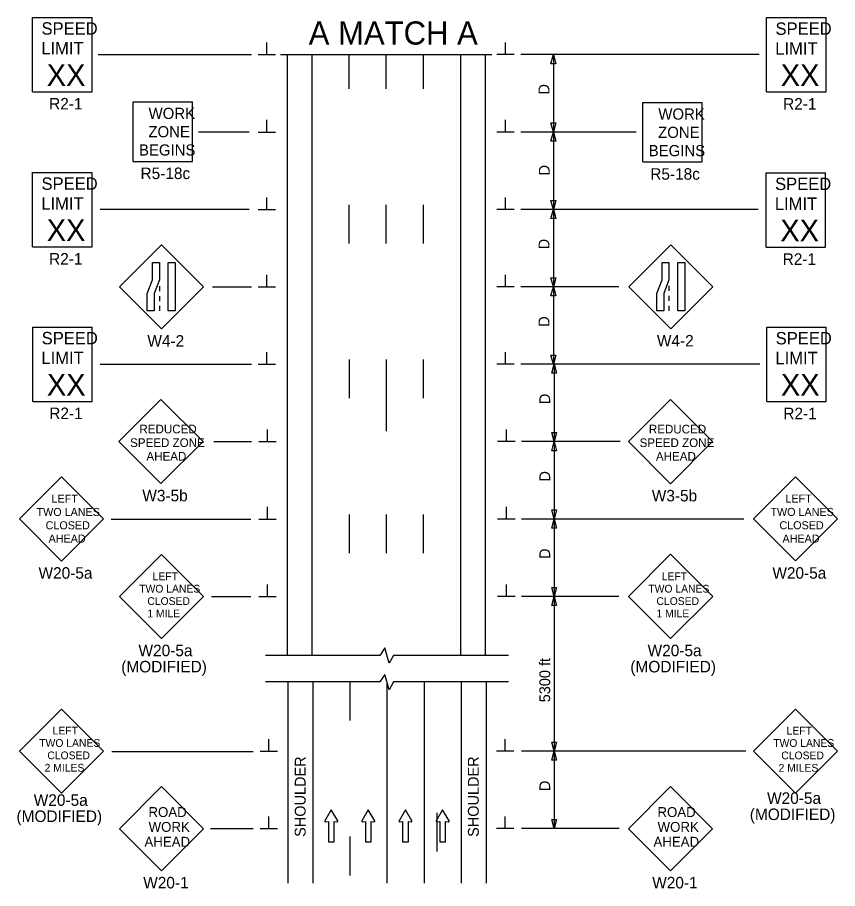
# Model space of a CAD drawing. Extents: x 16630 to 19509, y 5576 to 6998.
# Drawn here: x 17841 to 18371, y 6359 to 6921 of the extents above; entities that cross this region are included whole.
import ezdxf

# ---------------------------------------------------------------- set-up
doc = ezdxf.new("R2010")
doc.units = 0
for name, color, linetype in [('ALI_LEGAL_EX', 7, 'Continuous'), ('MT_SCRATCH_LEVEL_E', 7, 'Continuous'), ('PAVT_EDGE_EX', 7, 'Continuous'), ('TRAFFIC_SIGNS_PR', 7, 'Continuous'), ('TYPICAL_TEXT_DIMEN_PR', 7, 'Continuous')]:
    doc.layers.add(name, color=color, linetype=linetype)

msp = doc.modelspace()

# ---------------------------------------------------------------- linework, layer by layer
at = {"layer": 'ALI_LEGAL_EX'}
for p, q in [((18080.13, 6492.04), (18080.13, 6361.96)), ((18104.13, 6492.04), (18104.13, 6361.96))]:
    msp.add_line(p, q, dxfattribs=at)
for points in [[(18055.61, 6875.22), (18055.61, 6897.24)], [(18079.61, 6875.22), (18079.61, 6897.24)], [(18103.61, 6875.22), (18103.61, 6897.24)], [(18055.61, 6775.22), (18055.61, 6800.22)], [(18079.61, 6775.22), (18079.61, 6800.22)], [(18103.61, 6775.22), (18103.61, 6800.22)], [(18055.61, 6700.22), (18055.61, 6675.22)], [(18079.61, 6700.22), (18079.61, 6675.22)], [(18103.61, 6675.22), (18103.61, 6700.22)], [(18079.61, 6679.08), (18079.61, 6654.08)], [(18055.61, 6600.22), (18055.61, 6575.22)], [(18079.61, 6600.22), (18079.61, 6575.22)], [(18103.61, 6575.22), (18103.61, 6600.22)], [(18056.13, 6492.04), (18056.13, 6467.04)], [(18080.13, 6492.04), (18080.13, 6467.04)], [(18104.13, 6492.04), (18104.13, 6467.04)], [(18112.27, 6407.39), (18112.27, 6382.39)], [(18056.13, 6392.04), (18056.13, 6367.04)], [(18080.13, 6392.04), (18080.13, 6367.04)], [(18104.13, 6392.04), (18104.13, 6367.04)]]:
    msp.add_lwpolyline(points, dxfattribs=at)
at = {"layer": 'MT_SCRATCH_LEVEL_E'}
for p, q in [((18044.13, 6409.47), (18040.02, 6402.23)), ((18048.27, 6402.23), (18044.13, 6409.47)), ((18068.03, 6409.47), (18063.92, 6402.23)), ((18072.18, 6402.23), (18068.03, 6409.47)), ((18092.03, 6409.47), (18087.92, 6402.23)), ((18096.18, 6402.23), (18092.03, 6409.47)), ((18116.08, 6409.47), (18111.97, 6402.23)), ((18120.23, 6402.23), (18116.08, 6409.47)), ((18040.5, 6401.54), (18042.28, 6401.86)), ((18042.28, 6401.86), (18042.28, 6388.6)), ((18046.02, 6388.6), (18046.02, 6401.86)), ((18046.02, 6401.86), (18047.79, 6401.54)), ((18064.4, 6401.54), (18066.18, 6401.86)), ((18066.18, 6401.86), (18066.18, 6388.6)), ((18069.92, 6388.6), (18069.92, 6401.86)), ((18069.92, 6401.86), (18071.7, 6401.54)), ((18088.4, 6401.54), (18090.18, 6401.86)), ((18090.18, 6401.86), (18090.18, 6388.6)), ((18093.92, 6388.6), (18093.92, 6401.86)), ((18093.92, 6401.86), (18095.7, 6401.54)), ((18112.46, 6401.54), (18114.23, 6401.86)), ((18114.23, 6401.86), (18114.23, 6388.6)), ((18117.97, 6388.6), (18117.97, 6401.86)), ((18117.97, 6401.86), (18119.75, 6401.54)), ((18042.28, 6388.6), (18046.02, 6388.6)), ((18066.18, 6388.6), (18069.92, 6388.6)), ((18090.18, 6388.6), (18093.92, 6388.6)), ((18114.23, 6388.6), (18117.97, 6388.6))]:
    msp.add_line(p, q, dxfattribs=at)
for centre, start, end in [((18040.42, 6402), 150.4248, 279.9638), ((18047.86, 6402), 260.0362, 29.7731), ((18064.33, 6402), 150.4248, 279.9638), ((18071.77, 6402), 260.0362, 29.7731), ((18088.33, 6402), 150.4248, 279.9638), ((18095.77, 6402), 260.0362, 29.7731), ((18112.38, 6402), 150.4248, 279.9638), ((18119.82, 6402), 260.0362, 29.7731)]:
    msp.add_arc(centre, 0.463, start, end, dxfattribs=at)
at = {"layer": 'PAVT_EDGE_EX'}
for p, q in [((18015.61, 6897.24), (18015.61, 6509.16)), ((18031.61, 6897.24), (18031.61, 6509.16)), ((18127.61, 6897.24), (18127.61, 6509.16)), ((18143.61, 6897.24), (18143.61, 6509.16)), ((18016.13, 6492.02), (18016.13, 6361.96)), ((18032.13, 6492.02), (18032.13, 6361.96)), ((18128.13, 6492.02), (18128.13, 6361.96)), ((18144.13, 6492.02), (18144.13, 6361.96))]:
    msp.add_line(p, q, dxfattribs=at)
at = {"layer": 'TRAFFIC_SIGNS_PR'}
for p, q in [((17851.16, 6921.26), (17889.56, 6921.26)), ((17851.16, 6873.26), (17851.16, 6921.26)), ((17889.56, 6873.26), (17889.56, 6921.26)), ((18325.38, 6921.16), (18363.78, 6921.16)), ((18325.38, 6873.16), (18325.38, 6921.16)), ((18363.78, 6873.16), (18363.78, 6921.16)), ((17851.16, 6873.26), (17889.56, 6873.26)), ((18325.38, 6873.16), (18363.78, 6873.16)), ((17916.1, 6828.28), (17916.1, 6866.68)), ((17916.1, 6866.68), (17954.5, 6866.68)), ((17954.5, 6828.28), (17954.5, 6866.68)), ((18245.42, 6827.87), (18245.42, 6866.27)), ((18245.42, 6866.27), (18283.82, 6866.27)), ((18283.82, 6827.87), (18283.82, 6866.27)), ((17916.1, 6828.28), (17954.5, 6828.28)), ((18245.42, 6827.87), (18283.82, 6827.87)), ((17851.16, 6821.05), (17889.56, 6821.05)), ((17851.16, 6773.05), (17851.16, 6821.05)), ((17889.56, 6773.05), (17889.56, 6821.05)), ((18325.1, 6820.87), (18363.5, 6820.87)), ((18325.1, 6772.87), (18325.1, 6820.87)), ((18363.5, 6772.87), (18363.5, 6820.87)), ((17851.16, 6773.05), (17889.56, 6773.05)), ((17934.36, 6774.31), (17907.21, 6747.16)), ((17961.52, 6747.16), (17934.36, 6774.31)), ((18263.56, 6774.43), (18236.41, 6747.28)), ((18290.71, 6747.28), (18263.56, 6774.43)), ((18325.1, 6772.87), (18363.5, 6772.87)), ((17933.12, 6747.65), (17933.12, 6744.45)), ((18262.31, 6747.77), (18262.31, 6744.57)), ((17907.21, 6747.16), (17934.36, 6720.01)), ((17934.36, 6720.01), (17961.52, 6747.16)), ((18236.41, 6747.28), (18263.56, 6720.13)), ((18263.56, 6720.13), (18290.71, 6747.28)), ((17933.12, 6741.25), (17933.12, 6738.05)), ((18262.31, 6741.37), (18262.31, 6738.17)), ((17933.12, 6734.85), (17933.12, 6731.65)), ((18262.31, 6734.97), (18262.31, 6731.77)), ((17851.27, 6721.23), (17889.67, 6721.23)), ((17851.27, 6673.23), (17851.27, 6721.23)), ((17889.67, 6673.23), (17889.67, 6721.23)), ((18325.5, 6721.17), (18363.9, 6721.17)), ((18325.5, 6673.17), (18325.5, 6721.17)), ((18363.9, 6673.17), (18363.9, 6721.17)), ((17934.1, 6674.41), (17906.95, 6647.26)), ((17961.26, 6647.26), (17934.1, 6674.41)), ((18263.27, 6674.37), (18236.11, 6647.21)), ((18290.42, 6647.21), (18263.27, 6674.37)), ((17851.27, 6673.23), (17889.67, 6673.23)), ((18325.5, 6673.17), (18363.9, 6673.17)), ((17906.95, 6647.26), (17934.1, 6620.1)), ((17934.1, 6620.1), (17961.26, 6647.26)), ((18236.11, 6647.21), (18263.27, 6620.06)), ((18263.27, 6620.06), (18290.42, 6647.21)), ((17869.85, 6624.41), (17842.7, 6597.26)), ((17897.01, 6597.26), (17869.85, 6624.41)), ((18343.98, 6624.43), (18316.82, 6597.28)), ((18371.13, 6597.28), (18343.98, 6624.43)), ((17842.7, 6597.26), (17869.85, 6570.11)), ((17869.85, 6570.11), (17897.01, 6597.26)), ((18316.82, 6597.28), (18343.98, 6570.12)), ((18343.98, 6570.12), (18371.13, 6597.28)), ((17934.46, 6574.42), (17907.27, 6547.24)), ((17961.65, 6547.24), (17934.46, 6574.42)), ((18263.39, 6574.43), (18236.2, 6547.24)), ((18290.58, 6547.24), (18263.39, 6574.43)), ((17907.27, 6547.24), (17934.46, 6520.05)), ((17934.46, 6520.05), (17961.65, 6547.24)), ((18236.2, 6547.24), (18263.39, 6520.05)), ((18263.39, 6520.05), (18290.58, 6547.24)), ((17869.86, 6474.47), (17842.68, 6447.28)), ((17897.05, 6447.28), (17869.86, 6474.47)), ((18344.06, 6474.42), (18316.87, 6447.24)), ((18371.24, 6447.24), (18344.06, 6474.42)), ((17842.68, 6447.28), (17869.86, 6420.1)), ((17869.86, 6420.1), (17897.05, 6447.28)), ((18316.87, 6447.24), (18344.06, 6420.05)), ((18344.06, 6420.05), (18371.24, 6447.24)), ((17934.47, 6424.35), (17907.32, 6397.2)), ((17961.62, 6397.2), (17934.47, 6424.35)), ((18263.32, 6424.35), (18236.17, 6397.2)), ((18290.47, 6397.2), (18263.32, 6424.35)), ((17907.32, 6397.2), (17934.47, 6370.05)), ((17934.47, 6370.05), (17961.62, 6397.2)), ((18236.17, 6397.2), (18263.32, 6370.05)), ((18263.32, 6370.05), (18290.47, 6397.2))]:
    msp.add_line(p, q, dxfattribs=at)
for points in [[(17933.12, 6762.9), (17933.12, 6751.72), (17929.77, 6742.83), (17929.77, 6731.65), (17925.28, 6731.65), (17925.28, 6742.83), (17928.62, 6751.72), (17928.62, 6762.9)], [(17943.25, 6762.9), (17943.25, 6731.65), (17938.76, 6731.65), (17938.76, 6762.9)], [(18262.31, 6763.02), (18262.31, 6751.84), (18258.97, 6742.95), (18258.97, 6731.77), (18254.47, 6731.77), (18254.47, 6742.95), (18257.82, 6751.84), (18257.82, 6763.02)], [(18272.45, 6763.02), (18272.45, 6731.77), (18267.96, 6731.77), (18267.96, 6763.02)]]:
    msp.add_lwpolyline(points, close=True, dxfattribs=at)
at = {"layer": 'TYPICAL_TEXT_DIMEN_PR'}
for p, q in [((18002.48, 6897.24), (18002.48, 6905.02)), ((18156.73, 6897.24), (18156.73, 6905.02)), ((17893.57, 6897.24), (17992.61, 6897.24)), ((17996.86, 6897.24), (18008.11, 6897.24)), ((18011.28, 6897.24), (18147.93, 6897.24)), ((18162.36, 6897.24), (18151.11, 6897.24)), ((18320.48, 6897.24), (18166.61, 6897.24)), ((18186.04, 6891.37), (18187.61, 6897.24)), ((18187.61, 6897.24), (18187.61, 6847.24)), ((18187.61, 6897.24), (18189.18, 6891.37)), ((18187.61, 6891.37), (18186.04, 6891.37)), ((18189.18, 6891.37), (18187.61, 6891.37)), ((18002.48, 6847.24), (18002.48, 6855.02)), ((18156.73, 6847.24), (18156.73, 6855.02)), ((18187.61, 6847.24), (18186.04, 6853.1)), ((18186.04, 6853.1), (18187.61, 6853.1)), ((18187.61, 6853.1), (18189.18, 6853.1)), ((18189.18, 6853.1), (18187.61, 6847.24)), ((17991.11, 6847.24), (17958.31, 6847.24)), ((17996.86, 6847.24), (18008.11, 6847.24)), ((18162.36, 6847.24), (18151.11, 6847.24)), ((18241.03, 6847.24), (18166.61, 6847.24)), ((18186.04, 6841.37), (18187.61, 6847.24)), ((18187.61, 6847.24), (18189.18, 6841.37)), ((18187.61, 6847.24), (18187.61, 6787.24)), ((18187.61, 6841.37), (18186.04, 6841.37)), ((18189.18, 6841.37), (18187.61, 6841.37)), ((18002.48, 6797.24), (18002.48, 6805.02)), ((18156.73, 6797.24), (18156.73, 6805.02)), ((18187.61, 6797.24), (18186.04, 6803.1)), ((18186.04, 6803.1), (18187.61, 6803.1)), ((18187.61, 6803.1), (18189.18, 6803.1)), ((18189.18, 6803.1), (18187.61, 6797.24)), ((17991.11, 6797.24), (17894.89, 6797.24)), ((17996.86, 6797.24), (18008.11, 6797.24)), ((18162.36, 6797.24), (18151.11, 6797.24)), ((18319.93, 6797.24), (18166.61, 6797.24)), ((18186.04, 6791.37), (18187.61, 6797.24)), ((18187.61, 6797.24), (18187.61, 6747.24)), ((18187.61, 6797.24), (18189.18, 6791.37)), ((18187.61, 6791.37), (18186.04, 6791.37)), ((18189.18, 6791.37), (18187.61, 6791.37)), ((18002.48, 6747.24), (18002.48, 6755.02)), ((18156.73, 6747.24), (18156.73, 6755.02)), ((18187.61, 6747.24), (18186.04, 6753.1)), ((18186.04, 6753.1), (18187.61, 6753.1)), ((18187.61, 6753.1), (18189.18, 6753.1)), ((18189.18, 6753.1), (18187.61, 6747.24)), ((17967.34, 6747.24), (17992.61, 6747.24)), ((17996.86, 6747.24), (18008.11, 6747.24)), ((18162.36, 6747.24), (18151.11, 6747.24)), ((18229.94, 6747.24), (18166.61, 6747.24)), ((18186.04, 6741.37), (18187.61, 6747.24)), ((18187.61, 6747.24), (18187.61, 6697.24)), ((18187.61, 6747.24), (18189.18, 6741.37)), ((18187.61, 6741.37), (18186.04, 6741.37)), ((18189.18, 6741.37), (18187.61, 6741.37)), ((18002.48, 6697.24), (18002.48, 6705.02)), ((18156.73, 6697.24), (18156.73, 6705.02)), ((18187.61, 6697.24), (18186.04, 6703.1)), ((18186.04, 6703.1), (18187.61, 6703.1)), ((18187.61, 6703.1), (18189.18, 6703.1)), ((18189.18, 6703.1), (18187.61, 6697.24)), ((17894.89, 6697.24), (17992.61, 6697.24)), ((17996.86, 6697.24), (18008.11, 6697.24)), ((18162.36, 6697.24), (18151.11, 6697.24)), ((18320.93, 6697.24), (18166.61, 6697.24)), ((18186.56, 6691.37), (18188.13, 6697.24)), ((18188.13, 6697.24), (18188.13, 6647.24)), ((18188.13, 6697.24), (18189.7, 6691.37)), ((18188.13, 6691.37), (18186.56, 6691.37)), ((18189.7, 6691.37), (18188.13, 6691.37)), ((18003, 6647.24), (18003, 6655.02)), ((18157.25, 6647.24), (18157.25, 6655.02)), ((18188.13, 6647.24), (18186.56, 6653.1)), ((18186.56, 6653.1), (18188.13, 6653.1)), ((18188.13, 6653.1), (18189.7, 6653.1)), ((18189.7, 6653.1), (18188.13, 6647.24)), ((17968.25, 6647.24), (17992.61, 6647.24)), ((17997.38, 6647.24), (18008.63, 6647.24)), ((18162.88, 6647.24), (18151.63, 6647.24)), ((18230.83, 6647.24), (18167.13, 6647.24)), ((18186.56, 6641.37), (18188.13, 6647.24)), ((18188.13, 6647.24), (18188.13, 6597.24)), ((18188.13, 6647.24), (18189.7, 6641.37)), ((18188.13, 6641.37), (18186.56, 6641.37)), ((18189.7, 6641.37), (18188.13, 6641.37)), ((18003, 6597.24), (18003, 6605.02)), ((18157.25, 6597.24), (18157.25, 6605.02)), ((18188.13, 6597.24), (18186.56, 6603.1)), ((18186.56, 6603.1), (18188.13, 6603.1)), ((18188.13, 6603.1), (18189.7, 6603.1)), ((18189.7, 6603.1), (18188.13, 6597.24)), ((17901.84, 6597.24), (17992.08, 6597.24)), ((17997.38, 6597.24), (18008.63, 6597.24)), ((18162.88, 6597.24), (18151.63, 6597.24)), ((18310.77, 6597.24), (18167.13, 6597.24)), ((18186.56, 6591.37), (18188.13, 6597.24)), ((18188.13, 6597.24), (18188.13, 6547.24)), ((18188.13, 6597.24), (18189.7, 6591.37)), ((18188.13, 6591.37), (18186.56, 6591.37)), ((18189.7, 6591.37), (18188.13, 6591.37)), ((18003, 6547.24), (18003, 6555.02)), ((18157.25, 6547.24), (18157.25, 6555.02)), ((18188.13, 6547.24), (18186.56, 6553.1)), ((18186.56, 6553.1), (18188.13, 6553.1)), ((18188.13, 6553.1), (18189.7, 6553.1)), ((18189.7, 6553.1), (18188.13, 6547.24)), ((17966.8, 6547.24), (17992.08, 6547.24)), ((17997.38, 6547.24), (18008.63, 6547.24)), ((18162.88, 6547.24), (18151.63, 6547.24)), ((18229.89, 6547.24), (18167.13, 6547.24)), ((18186.56, 6541.37), (18188.13, 6547.24)), ((18188.13, 6547.24), (18188.13, 6447.24)), ((18188.13, 6547.24), (18189.7, 6541.37)), ((18188.13, 6541.37), (18186.56, 6541.37)), ((18189.7, 6541.37), (18188.13, 6541.37)), ((18078.8, 6513.96), (18075.54, 6509.16)), ((18081.54, 6504.02), (18078.8, 6513.96)), ((18075.54, 6509.16), (18001.63, 6509.16)), ((18084.28, 6509.16), (18081.54, 6504.02)), ((18158.63, 6509.16), (18084.28, 6509.16)), ((18078.8, 6496.82), (18075.54, 6492.02)), ((18081.54, 6486.88), (18078.8, 6496.82)), ((18075.54, 6492.02), (18001.63, 6492.02)), ((18084.28, 6492.02), (18081.54, 6486.88)), ((18158.63, 6492.02), (18084.28, 6492.02)), ((18003.75, 6447.24), (18003.75, 6455.02)), ((18156.5, 6447.24), (18156.5, 6455.02)), ((18188.13, 6447.24), (18186.56, 6453.1)), ((18186.56, 6453.1), (18188.13, 6453.1)), ((18188.13, 6453.1), (18189.7, 6453.1)), ((18189.7, 6453.1), (18188.13, 6447.24)), ((17902.39, 6447.08), (17993.62, 6447.08)), ((17998.13, 6447.24), (18009.38, 6447.24)), ((18162.13, 6447.24), (18150.88, 6447.24)), ((18312.04, 6447.24), (18167.13, 6447.24)), ((18186.56, 6441.37), (18188.13, 6447.24)), ((18188.13, 6447.24), (18188.13, 6397.24)), ((18188.13, 6447.24), (18189.7, 6441.37)), ((18188.13, 6441.37), (18186.56, 6441.37)), ((18189.7, 6441.37), (18188.13, 6441.37)), ((18003.75, 6397.24), (18003.75, 6405.02)), ((18156.5, 6397.24), (18156.5, 6405.02)), ((18188.13, 6397.24), (18186.56, 6403.1)), ((18186.56, 6403.1), (18188.13, 6403.1)), ((18188.13, 6403.1), (18189.7, 6403.1)), ((18189.7, 6403.1), (18188.13, 6397.24)), ((17966.08, 6397.24), (17993.62, 6397.24)), ((17998.13, 6397.24), (18009.38, 6397.24)), ((18162.13, 6397.24), (18150.88, 6397.24)), ((18230.07, 6397.24), (18167.13, 6397.24))]:
    msp.add_line(p, q, dxfattribs=at)

# ---------------------------------------------------------------- texts
at = {"layer": 'TRAFFIC_SIGNS_PR'}
for s, height, p in [('SPEED', 8, (17856.93, 6910.13)), ('SPEED', 8, (18331.15, 6910.02)), ('LIMIT', 8, (17856.77, 6897.33)), ('LIMIT', 8, (18330.98, 6897.22)), ('XX', 14.031, (17860.28, 6877.02)), ('XX', 14.031, (18334.49, 6876.91)), ('R2-1', 7.44, (17861.84, 6861.82)), ('R2-1', 7.44, (18336.06, 6861.72)), ('WORK', 7.217, (17926.1, 6855.65)), ('WORK', 7.217, (18255.42, 6855.23)), ('ZONE', 7.217, (17925.98, 6843.84)), ('ZONE', 7.217, (18255.3, 6843.42)), ('BEGINS', 7.217, (17919.91, 6832.03)), ('BEGINS', 7.217, (18249.23, 6831.61)), ('R5-18c', 7.44, (17920.91, 6816.84)), ('R5-18c', 7.44, (18250.23, 6816.43)), ('SPEED', 8, (17856.93, 6809.91)), ('SPEED', 8, (18330.87, 6809.74)), ('LIMIT', 8, (17856.77, 6797.11)), ('LIMIT', 8, (18330.71, 6796.94)), ('XX', 14.031, (17860.28, 6776.81)), ('XX', 14.031, (18334.22, 6776.63)), ('R2-1', 7.44, (17861.84, 6761.61)), ('R2-1', 7.44, (18335.78, 6761.43)), ('SPEED', 8, (17857.04, 6710.09)), ('W4-2', 7.44, (17925.32, 6708.57)), ('W4-2', 7.44, (18254.52, 6708.69)), ('SPEED', 8, (18331.27, 6710.04)), ('LIMIT', 8, (17856.88, 6697.29)), ('LIMIT', 8, (18331.11, 6697.24)), ('XX', 14.031, (17860.38, 6676.99)), ('XX', 14.031, (18334.61, 6676.93)), ('R2-1', 7.44, (17861.95, 6661.79)), ('R2-1', 7.44, (18336.18, 6661.73)), ('REDUCED', 5.6, (17920.16, 6652.57)), ('REDUCED', 5.6, (18249.32, 6652.52)), ('SPEED ZONE', 5.6, (17914.15, 6643.77)), ('SPEED ZONE', 5.6, (18243.32, 6643.72)), ('AHEAD', 5.6, (17924.71, 6634.97)), ('AHEAD', 5.6, (18253.88, 6634.92)), ('LEFT', 5.2, (17863.39, 6607.79)), ('W3-5b', 7.44, (17922.06, 6608.66)), ('W3-5b', 7.44, (18251.22, 6608.62)), ('LEFT', 5.2, (18337.51, 6607.81)), ('TWO LANES', 5.2, (17853.72, 6599.19)), ('TWO LANES', 5.2, (18327.84, 6599.21)), ('CLOSED', 5.2, (17859.57, 6590.59)), ('CLOSED', 5.2, (18333.69, 6590.61)), ('AHEAD', 5.2, (17861.51, 6581.99)), ('AHEAD', 5.2, (18335.64, 6582.01)), ('W20-5a', 7.44, (17854.99, 6558.67)), ('LEFT', 5.006, (17928.7, 6557.73)), ('LEFT', 5.006, (18257.63, 6557.73)), ('W20-5a', 7.44, (18329.12, 6558.68)), ('TWO LANES', 5.006, (17920.05, 6549.72)), ('TWO LANES', 5.006, (18248.98, 6549.72)), ('CLOSED', 5.006, (17925.28, 6541.71)), ('CLOSED', 5.006, (18254.21, 6541.72)), ('1 MILE', 5.006, (17925.28, 6533.71)), ('1 MILE', 5.006, (18254.21, 6533.71)), ('W20-5a', 7.449, (17919.58, 6508.6)), ('W20-5a', 7.449, (18248.51, 6508.6)), ('(MODIFIED)', 7.449, (17908.42, 6498.15)), ('(MODIFIED)', 7.449, (18237.35, 6498.15)), ('LEFT', 5.006, (17864.11, 6458.08)), ('LEFT', 5.006, (18338.3, 6458.03)), ('TWO LANES', 5.006, (17855.46, 6450.07)), ('TWO LANES', 5.006, (18329.65, 6450.02)), ('CLOSED', 5.006, (17860.69, 6442.06)), ('CLOSED', 5.006, (18334.88, 6442.02)), ('2 MILES', 5.006, (17858.94, 6434.05)), ('2 MILES', 5.006, (18333.13, 6434.01)), ('W20-5a', 7.449, (17851.9, 6411.95)), ('W20-5a', 7.449, (18325.69, 6413.21)), ('ROAD', 6.4, (17926.01, 6404.74)), ('ROAD', 6.4, (18254.86, 6404.74)), ('(MODIFIED)', 7.449, (18314.53, 6402.76)), ('(MODIFIED)', 7.449, (17840.74, 6401.5)), ('WORK', 6.4, (17926.12, 6395.14)), ('WORK', 6.4, (18254.97, 6395.14)), ('AHEAD', 6.4, (17923.43, 6385.54)), ('AHEAD', 6.4, (18252.28, 6385.54)), ('W20-1', 7.44, (17922.64, 6358.61)), ('W20-1', 7.44, (18251.49, 6358.61))]:
    msp.add_text(s, height=height, dxfattribs=at).set_placement(p)
at = {"layer": 'TYPICAL_TEXT_DIMEN_PR'}
msp.add_text('A MATCH A', height=15, dxfattribs=at).set_placement((18029.57, 6903.7))
for s, p in [('D', (18185.05, 6871.45)), ('D', (18185.26, 6819.17)), ('D', (18185.05, 6771.45)), ('D', (18185.05, 6721.45)), ('D', (18185.57, 6671.45)), ('D', (18185.57, 6621.45)), ('D', (18185.57, 6571.45)), ('5300 ft', (18185.57, 6478.84)), ('SHOULDER', (18027.55, 6391.89)), ('SHOULDER', (18139.41, 6391.89)), ('D', (18185.57, 6421.46))]:
    msp.add_text(s, height=7, rotation=90, dxfattribs=at).set_placement(p)

doc.saveas('drawing.dxf')
